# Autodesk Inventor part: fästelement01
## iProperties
Shininess: 64.0
Length Units: 11269
Angle Units: 11279
Time Units: 11290
Mass Units: 11283
Length Display Precision: 3
Angle Display Precision: 2
Created: 2001-12
Part Number: fästelement01
Material: Steel, Mild
Document SubType Name: Modeling
Designer: Tobben
Density: 1 g/cm^3
Density: 0.0
Volumn: 0.0
Area: 0.0
PropertySet Name: Model Information
Control State: 0
Master: False
Checked Out: False
Author: Tobben
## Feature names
1. Extrusion1
2. Extrusion2
3. Fillet1
4. Extrusion3
